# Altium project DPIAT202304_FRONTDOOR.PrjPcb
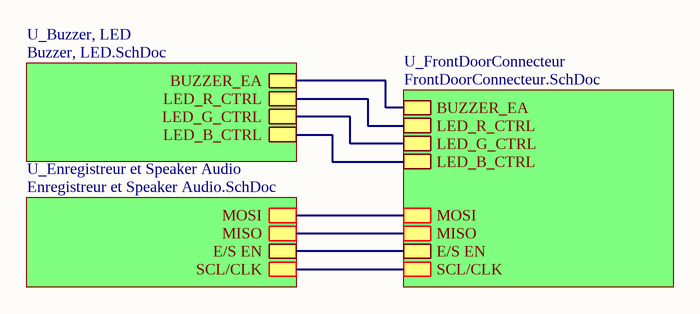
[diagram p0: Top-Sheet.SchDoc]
4 sheets, 43 parts. Net scope: hierarchical (ports join the sheet entries above them; power ports are global).
Sheets:
  Top-Sheet.SchDoc
    U_FrontDoorConnecteur = FrontDoorConnecteur.SchDoc
    U_Buzzer, LED = Buzzer, LED.SchDoc
    U_Enregistreur et Speaker Audio = Enregistreur et Speaker Audio.SchDoc

## Sheet Top-Sheet.SchDoc
size Letter; Organization: Cegep Limoilou; Address1: 1300, 8e Avenue; Address2: Québec, QC; Address3: Canada; Address4: G1J 5L5; Revision: Enseignants; SheetNumber: 1; SheetTotal: 4; Conception: Ilyes Gharmoul; Titre: Connecteur FrontDoor; Modification: Ilyes G

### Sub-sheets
U_Buzzer, LED = Buzzer, LED.SchDoc: BUZZER_EA, LED_R_CTRL, LED_G_CTRL, LED_B_CTRL
U_Enregistreur et Speaker Audio = Enregistreur et Speaker Audio.SchDoc: MOSI, MISO, SCL/CLK, E/S EN
U_FrontDoorConnecteur = FrontDoorConnecteur.SchDoc: BUZZER_EA, LED_R_CTRL, LED_G_CTRL, LED_B_CTRL, MOSI, MISO, E/S EN, SCL/CLK

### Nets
LED_B_CTRL: sheet U_FrontDoorConnecteur/LED_B_CTRL, sheet U_Buzzer, LED/LED_B_CTRL
LED_G_CTRL: sheet U_FrontDoorConnecteur/LED_G_CTRL, sheet U_Buzzer, LED/LED_G_CTRL
LED_R_CTRL: sheet U_FrontDoorConnecteur/LED_R_CTRL, sheet U_Buzzer, LED/LED_R_CTRL
NetJ?#1_5: sheet U_FrontDoorConnecteur/E/S EN, sheet U_Enregistreur et Speaker Audio/E/S EN
NetJ?#1_6: sheet U_FrontDoorConnecteur/MISO, sheet U_Enregistreur et Speaker Audio/MISO
NetJ?#1_7: sheet U_FrontDoorConnecteur/MOSI, sheet U_Enregistreur et Speaker Audio/MOSI
NetJ?#1_8: sheet U_FrontDoorConnecteur/BUZZER_EA, sheet U_Buzzer, LED/BUZZER_EA
NetJ?#1_9: sheet U_FrontDoorConnecteur/SCL/CLK, sheet U_Enregistreur et Speaker Audio/SCL/CLK

## Sheet FrontDoorConnecteur.SchDoc
size Letter; Organization: Cegep Limoilou; Address1: 1300, 8e Avenue; Address2: Québec, QC; Address3: Canada; Address4: G1J 5L5; Revision: Enseignants; SheetNumber: 2; SheetTotal: 4; Conception: Ilyes Gharmoul; Titre: Connecteur FrontDoor; Modification: Ilyes G
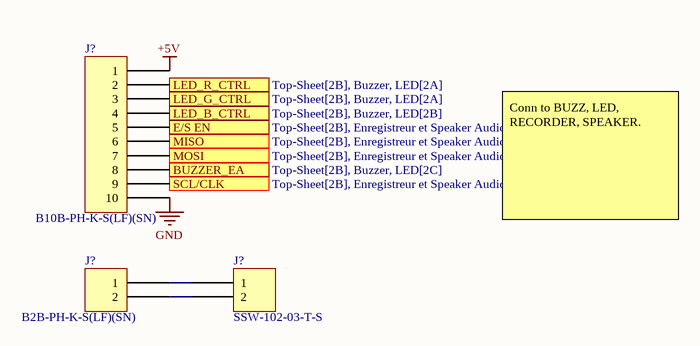
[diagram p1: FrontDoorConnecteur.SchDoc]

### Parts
(Parts that share a designator on the sheet are numbered #1, #2 ... from top to bottom, then left to right.)
J?#1  B10B-PH-K-S(LF)(SN)  [JST B10B-PH-K]
J?#2  B2B-PH-K-S(LF)(SN)  [JST B2B-PH-K]
J?#3  SSW-102-03-T-S  [SAMTEC SSW-102-03-T-S]

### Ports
BUZZER_EA (see Top-Sheet[2B], Buzzer, LED[2C]), E/S EN (see Top-Sheet[2B], Enregistreur et Speaker Audio[2B]), LED_B_CTRL (see Top-Sheet[2B], Buzzer, LED[2B]), LED_G_CTRL (see Top-Sheet[2B], Buzzer, LED[2A]), LED_R_CTRL (see Top-Sheet[2B], Buzzer, LED[2A]), MISO (see Top-Sheet[2B], Enregistreur et Speaker Audio[2B]), MOSI (see Top-Sheet[2B], Enregistreur et Speaker Audio[2B]), SCL/CLK (see Top-Sheet[2B], Enregistreur et Speaker Audio[2B])

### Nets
+5V: J?#1.1
GND: J?#1.10
LED_B_CTRL: J?#1.4 ; port LED_B_CTRL
LED_G_CTRL: J?#1.3 ; port LED_G_CTRL
LED_R_CTRL: J?#1.2 ; port LED_R_CTRL
NetJ?#1_5: J?#1.5 ; port E/S EN
NetJ?#1_6: J?#1.6 ; port MISO
NetJ?#1_7: J?#1.7 ; port MOSI
NetJ?#1_8: J?#1.8 ; port BUZZER_EA
NetJ?#1_9: J?#1.9 ; port SCL/CLK
NetJ?#2_1: J?#2.1 J?#3.1
NetJ?#2_2: J?#2.2 J?#3.2

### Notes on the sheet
- Conn to BUZZ, LED, RECORDER, SPEAKER.

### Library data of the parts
J?#1 = B10B-PH-K-S(LF)(SN): CONN HEADER VERT 10POS 2MM; Manufacturer: JST Sales America Inc.; Contact Length - Mating: 0.130" (3.30mm); Contact Length - Post: 0.134" (3.40mm); Current Rating (Amps): 2A; Material Flammability Rating: UL94 V-0; Number of Positions: 10; Number of Positions Loaded: All; Overall Contact Length: 0.333" (8.45mm); Pitch - Mating: 0.079" (2.00mm); Shrouding: Shrouded - 4 Wall; Style: Board to Cable/Wire; Voltage Rating: 100V
J?#2 = B2B-PH-K-S(LF)(SN): CONN HEADER VERT 2POS 2MM; Manufacturer: JST Sales America Inc.; Contact Length - Mating: 0.130" (3.30mm); Contact Length - Post: 0.134" (3.40mm); Current Rating (Amps): 2A; Material Flammability Rating: UL94 V-0; Number of Positions: 2; Number of Positions Loaded: All; Overall Contact Length: 0.333" (8.45mm); Pitch - Mating: 0.079" (2.00mm); Shrouding: Shrouded - 4 Wall; Style: Board to Cable/Wire; Voltage Rating: 100V
J?#3 = SSW-102-03-T-S: CONN RCPT 2POS 0.1 TIN PCB; Manufacturer: Samtec Inc.; Connector Type: Receptacle; Current Rating (Amps): 5.7A per Contact; Material Flammability Rating: UL94 V-0; Number of Positions: 2; Number of Positions Loaded: All; Style: Board to Board or Cable

## Sheet Buzzer, LED.SchDoc
size Letter; Organization: Cegep Limoilou; Address1: 1300, 8e Avenue; Address2: Québec, QC; Address3: Canada; Address4: G1J 5L5; Revision: Enseignants; SheetNumber: 3; SheetTotal: 4; Conception: Ilyes Gharmoul; Titre: Buzzer LED Infrarrouge; Modification: Ilyes G
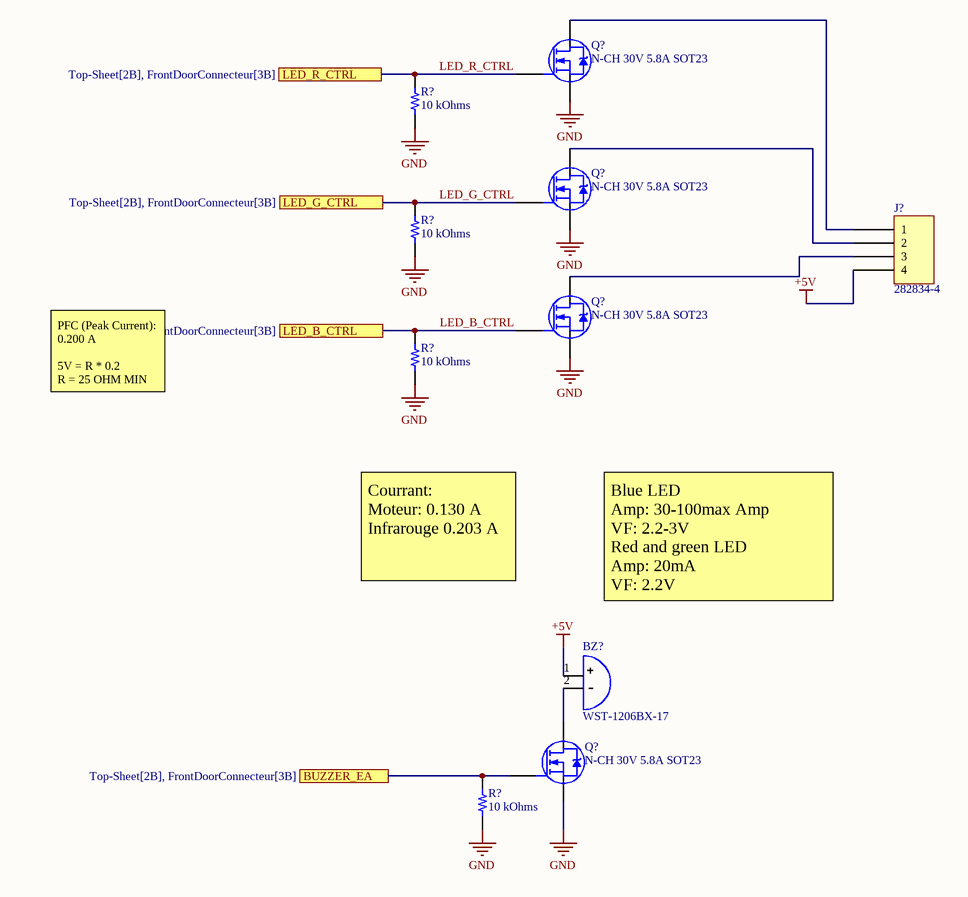
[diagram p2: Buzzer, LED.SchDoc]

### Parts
(Parts that share a designator on the sheet are numbered #1, #2 ... from top to bottom, then left to right.)
BZ?  WST-1206BX-17  [KCG1206-DSF]
J?#4  282834-4  [TE 282834-4]
Q?#1  N-CH 30V 5.8A SOT23  [N CHANNEL 30V 5.8A]
Q?#2  N-CH 30V 5.8A SOT23  [N CHANNEL 30V 5.8A]
Q?#3  N-CH 30V 5.8A SOT23  [N CHANNEL 30V 5.8A]
Q?#4  N-CH 30V 5.8A SOT23  [N CHANNEL 30V 5.8A]
R?#1  10 kOhms  [RES 0603]
R?#2  10 kOhms  [RES 0603]
R?#3  10 kOhms  [RES 0603]
R?#4  10 kOhms  [RES 0603]

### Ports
BUZZER_EA (see Top-Sheet[2B], FrontDoorConnecteur[3B]), LED_B_CTRL (see Top-Sheet[2B], FrontDoorConnecteur[3B]), LED_G_CTRL (see Top-Sheet[2B], FrontDoorConnecteur[3B]), LED_R_CTRL (see Top-Sheet[2B], FrontDoorConnecteur[3B])

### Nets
+5V: BZ?.1 J?#4.4
GND: Q?#1.2(S) Q?#2.2(S) Q?#3.2(S) Q?#4.2(S) R?#1.1 R?#2.1 R?#3.1 R?#4.1
LED_B_CTRL: Q?#3.1(G) R?#3.2 ; port LED_B_CTRL
LED_G_CTRL: Q?#2.1(G) R?#2.2 ; port LED_G_CTRL
LED_R_CTRL: R?#1.2 ; port LED_R_CTRL
NetBZ?_2: BZ?.2 Q?#4.3(D)
NetJ?#1_8: Q?#4.1(G) R?#4.2 ; port BUZZER_EA
NetJ?#4_1: J?#4.1 Q?#1.3(D)
NetJ?#4_2: J?#4.2 Q?#2.3(D)
NetJ?#4_3: J?#4.3 Q?#3.3(D)

Not connected (* = marked no-connect by the designer): Q?#1 1(G)

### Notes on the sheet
- PFC (Peak Current): 0.200 A
  5V = R * 0.2
  R = 25 OHM MIN
- Courrant:
  Moteur: 0.130 A
  Infrarouge 0.203 A
- Blue LED
  Amp: 30-100max Amp
  VF: 2.2-3V
  Red and green LED
  Amp: 20mA
  VF: 2.2V

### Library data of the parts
BZ? = WST-1206BX-17: Buzzers Indicator, Internally Driven Magnetic 5 V 30mA 3.1kHz 83dB @ 5V, 10cm Through Hole PC Pins
J?#4 = 282834-4: TERM BLK 4P SIDE ENT 2.54MM PCB; Manufacturer: TE Connectivity AMP Connectors; Current: 10A; Mating Orientation: Horizontal with Board; Number of Levels: 1; Pitch: 0.100" (2.54mm); Positions Per Level: 4; Voltage: 150V; Wire Gauge: 16-30 AWG; Wire Termination: Screw - Rising Cage Clamp
Q?#1-Q?#4 = TRANS N-CHANNEL 30V 5.8A SOT23: N-Channel 5.8A (Tj) 350mW Surface Mount SOT-23; Manufacturer Part Number 1: SI3404-TP; Manufacturer: MCC
R?#1-R?#4 = 0603 10K 1% 1/4W TC: RESHIGHPOWER 0603 10K 1% 1/4W TC; Manufacturer Part Number 1: CMP0603-FX-1002ELF; Manufacturer: Bourns Inc.; Power (Watts): 0.25W, 1/4W; Temperature Coefficient: ±100ppm/°C

## Sheet Enregistreur et Speaker Audio.SchDoc
size Letter; Organization: Cegep Limoilou; Address1: 1300, 8e Avenue; Address2: Québec, QC; Address3: Canada; Address4: G1J 5L5; Revision: Enseignants; SheetNumber: 4; SheetTotal: 9; Conception: Ilyes Gharmoul; Titre: Enregistreur et Speaker; Modification: Ilyes G
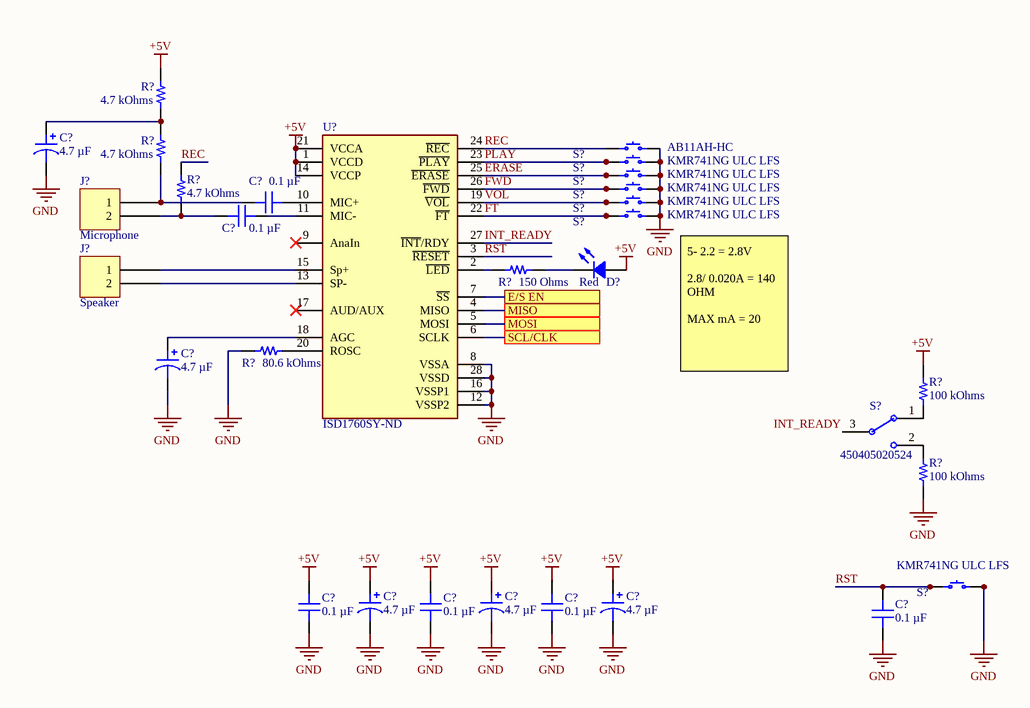
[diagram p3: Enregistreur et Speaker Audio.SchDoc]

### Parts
(Parts that share a designator on the sheet are numbered #1, #2 ... from top to bottom, then left to right.)
C?#1  4.7 µF  [CAP ALSMD 4.3MM H5.4MM]
C?#2  0.1 µF  [CAP 0603_1608]
C?#3  0.1 µF  [CAP 0603_1608]
C?#4  4.7 µF  [CAP ALSMD 4.3MM H5.4MM]
C?#5  0.1 µF  [CAP 0603_1608]
C?#6  4.7 µF  [CAP ALSMD 4.3MM H5.4MM]
C?#7  0.1 µF  [CAP 0603_1608]
C?#8  4.7 µF  [CAP ALSMD 4.3MM H5.4MM]
C?#9  0.1 µF  [CAP 0603_1608]
C?#10  4.7 µF  [CAP ALSMD 4.3MM H5.4MM]
C?#11  0.1 µF  [CAP 0603_1608]
D?  Red  [LED 0603_1608 RED]
J?#5  Microphone  [TE 282834-2]
J?#6  Speaker  [TE 282834-2]
R?#5  4.7 kOhms  [RES 0603_1608]
R?#6  4.7 kOhms  [RES 0603_1608]
R?#7  4.7 kOhms  [RES 0603_1608]
R?#8  150 Ohms  [RES 0603_1608]
R?#9  80.6 kOhms  [RES 0603_1608]
R?#10  100 kOhms  [RES 0603_1608]
R?#11  100 kOhms  [RES 0603_1608]
S?#1  AB11AH-HC  [NKK AB11AH-HC]
S?#2  KMR741NG ULC LFS  [C&K KMR7]
S?#3  KMR741NG ULC LFS  [C&K KMR7]
S?#4  KMR741NG ULC LFS  [C&K KMR7]
S?#5  KMR741NG ULC LFS  [C&K KMR7]
S?#6  KMR741NG ULC LFS  [C&K KMR7]
S?#7  450405020524  [WURTH WS-SLSU 450405020524]
S?#8  KMR741NG ULC LFS  [C&K KMR7]
U?  Supplier Part Number 1: ISD1760SY-ND  [ISD1760SY]  (hidden comment: ISD1760SY)

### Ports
E/S EN, MISO, MOSI, SCL/CLK

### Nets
+5V: C?#5.2 C?#6.1 C?#7.2 C?#8.1 C?#9.2 C?#10.1 D?.1 R?#5.2 R?#10.2 U?.1(VCCD) U?.14(VCCP) U?.21(VCCA)
GND: C?#1.2 C?#4.2 C?#5.1 C?#6.2 C?#7.1 C?#8.2 C?#9.1 C?#10.2 C?#11.1 R?#9.1 R?#11.1 S?#1.2 S?#2.3 S?#2.4 S?#3.3 S?#3.4 S?#4.3 S?#4.4 S?#5.3 S?#5.4 S?#6.3 S?#6.4 S?#8.3 S?#8.4 U?.8(VSSA) U?.12(VSSP2) U?.16(VSSP1) U?.28(VSSD)
ERASE: S?#3.1 S?#3.2 U?.25(~{ERASE})
FT: S?#6.1 S?#6.2 U?.22(~{FT})
FWD: S?#4.1 S?#4.2 U?.26(~{FWD})
INT_READY: S?#7.3(COM) U?.27(~{INT}/RDY)
PLAY: S?#2.1 S?#2.2 U?.23(~{PLAY})
REC: R?#7.2 S?#1.1 U?.24(~{REC})
RST: C?#11.2 S?#8.1 S?#8.2 U?.3(~{RESET})
VOL: S?#5.1 S?#5.2 U?.19(~{VOL})
NetC?#1_1: C?#1.1 R?#5.1 R?#6.2
NetC?#2_1: C?#2.1 U?.10(MIC+)
NetC?#2_2: C?#2.2 J?#5.1 R?#6.1
NetC?#3_1: C?#3.1 U?.11(MIC-)
NetC?#3_2: C?#3.2 J?#5.2 R?#7.1
NetC?#4_1: C?#4.1 U?.18(AGC)
NetD?_2: D?.2 R?#8.2
NetJ?#1_5: U?.7(~{SS}) ; port E/S EN
NetJ?#1_6: U?.4(MISO) ; port MISO
NetJ?#1_7: U?.5(MOSI) ; port MOSI
NetJ?#1_9: U?.6(SCLK) ; port SCL/CLK
NetJ?#6_1: J?#6.1 U?.15(Sp+)
NetJ?#6_2: J?#6.2 U?.13(SP-)
NetR?#8_1: R?#8.1 U?.2(~{LED})
NetR?#9_2: R?#9.2 U?.20(ROSC)
NetR?#10_1: R?#10.1 S?#7.1
NetR?#11_2: R?#11.2 S?#7.2

Not connected (* = marked no-connect by the designer): U? 9(AnaIn)* 17(AUD/AUX)*

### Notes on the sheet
- (near S?#6) 5- 2.2 = 2.8V
  2.8/ 0.020A = 140 OHM
  MAX mA = 20

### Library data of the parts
C?#1 C?#4 C?#6 C?#8 C?#10 = EMVE350ADA4R7MD55G: CAP ALUM 4.7UF 20% 35V SMD; manufacturer: United Chemi-Con; Lifetime @ Temp.: 1000 Hrs @ 105°C; Polarization: Polar; Ripple Current @ Low Frequency: 16 mA @ 120 Hz; Surface Mount Land Size: 0.169" L x 0.169" W (4.30mm x 4.30mm)
C?#2 C?#3 C?#5 C?#7 C?#9 C?#11 = CS0603KRX7R7BB104: CAP CER 0.1UF 16V X7R 0603; manufacturer: Yageo; Tolerance: ±10%
D? = BL-HUB36A-AV-TRB: 0603 RED; Manufacturer: American Bright Optoelectronics Corporation; Configuration: Standard; Current - Test: 20mA; Lens Color: Colorless; Lens Style: Rectangle with Flat Top; Lens Transparency: Clear; Millicandela Rating: 94mcd; Viewing Angle: 120°; Voltage - Forward (Vf) (Typ): 2.2V; Wavelength - Dominant: 632nm; Wavelength - Peak: 645nm
J?#5 J?#6 = 282834-2: TERM BLK 2P SIDE ENT 2.54MM PCB; Manufacturer: TE Connectivity AMP Connectors; Current: 10A; Mating Orientation: Horizontal with Board; Number of Levels: 1; Pitch: 0.100" (2.54mm); Positions Per Level: 2; Voltage: 150V; Wire Gauge: 16-30 AWG; Wire Termination: Screw - Rising Cage Clamp
R?#5-R?#7 = RMCF0603FT4K70: RES 4.7K OHM 1% 1/10W 0603; Manufacturer: Stackpole Electronics Inc; Power (Watts): 0.1W, 1/10W; Temperature Coefficient: ±100ppm/°C
R?#8 = MCT0603MD1500BP100: RES SMD 150 OHM 0.1% 1/8W 0603; Manufacturer: Vishay Beyschlag; Power (Watts): 0.125W, 1/8W; Temperature Coefficient: ±25ppm/°C
R?#9 = RCS060380K6FKEA: RES SMD 80.6K OHM 1% 1/4W 0603; Manufacturer: Vishay Dale; Power (Watts): 0.25W, 1/4W; Temperature Coefficient: ±100ppm/°C
R?#10 R?#11 = CMP0603AFX-1003ELF: RESHIGHPOWERA 0603 100K 1% 1/4W; Manufacturer: Bourns Inc.; Power (Watts): 0.25W, 1/4W; Temperature Coefficient: ±100ppm/°C
S?#1 = AB11AH-HC: SWITCH PUSH SPST-NO 0.4VA 28V; Manufacturer: NKK Switches; Actuator Type: Round, Button; Color - Actuator/Cap: Red; Current Rating (Amps): 0.4VA (AC/DC); Switch Function: Off-Mom
S?#2-S?#6 S?#8 = KMR741NG ULC LFS: SWITCH TACTILE SPST-NO 50MA 32V; Manufacturer: C&K; Actuator Height off PCB, Vertical: 2.50mm; Actuator Orientation: Top Actuated; Actuator Type: Standard; Contact Rating @ Voltage: 0.05A @ 32VDC; Illumination: Non-Illuminated; Ingress Protection: IP67 - Dust Tight, Waterproof; Operating Force: 400gf; Outline: 4.20mm x 2.80mm; Switch Function: Off-Mom
S?#7 = 450405020524: SMT 8.7 X 3.0 MM MINI SLIDE SWIT; Manufacturer: Würth Elektronik; Rated Current: 300mA; Rated Voltage: 5VDC; Switching Function: On-On; Circuit: SPDT; Actuator Length: 2.00mm; Actuator Type: Standard; Contact Timing: Non-Shorting (BBM); Current Rating (Amps): 300mA (DC); Voltage Rating - DC: 5 V
U? = ISD1760SY: Voice Record/Playback IC Multiple Message 40 ~ 120 Sec Pushbutton, SPI 28-SOIC

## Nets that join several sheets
+5V: FrontDoorConnecteur (J?#1.1), Buzzer, LED (BZ?.1 J?#4.4), Enregistreur et Speaker Audio (12 pins)
GND: FrontDoorConnecteur (J?#1.10), Buzzer, LED (8 pins), Enregistreur et Speaker Audio (28 pins)
LED_B_CTRL: FrontDoorConnecteur (J?#1.4), Buzzer, LED (Q?#3.1 R?#3.2)
LED_G_CTRL: FrontDoorConnecteur (J?#1.3), Buzzer, LED (Q?#2.1 R?#2.2)
LED_R_CTRL: FrontDoorConnecteur (J?#1.2), Buzzer, LED (R?#1.2)
NetJ?#1_5: FrontDoorConnecteur (J?#1.5), Enregistreur et Speaker Audio (U?.7)
NetJ?#1_6: FrontDoorConnecteur (J?#1.6), Enregistreur et Speaker Audio (U?.4)
NetJ?#1_7: FrontDoorConnecteur (J?#1.7), Enregistreur et Speaker Audio (U?.5)
NetJ?#1_8: FrontDoorConnecteur (J?#1.8), Buzzer, LED (Q?#4.1 R?#4.2)
NetJ?#1_9: FrontDoorConnecteur (J?#1.9), Enregistreur et Speaker Audio (U?.6)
